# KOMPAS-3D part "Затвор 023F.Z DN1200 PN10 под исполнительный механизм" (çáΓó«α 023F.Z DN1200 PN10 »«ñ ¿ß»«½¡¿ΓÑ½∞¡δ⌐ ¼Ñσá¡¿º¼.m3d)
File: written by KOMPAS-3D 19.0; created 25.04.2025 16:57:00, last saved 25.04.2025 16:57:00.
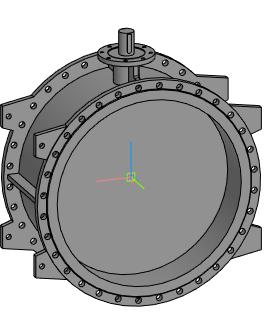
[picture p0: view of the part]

Document properties: Автор: Евгений; Полное имя файла: E:\Dendor Работа Сачек\3D для проекитирвщиков\1.7 Тип 023F.Z Затвор дисковый поворотный фланцевый с двумя эксцентриками\stp_Тип 023F.Z. Затвор под исполн. механизм\Затвор 023F.Z DN1200 PN10 под исполнительный механизм.m3d

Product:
- Part/product: Затвор 023F.Z DN1200 PN10 под исполнительный механизм

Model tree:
1. Операция без истории:1  (labels: Затвор 023F.Z DN1200 PN10 под исполнительный механизм)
